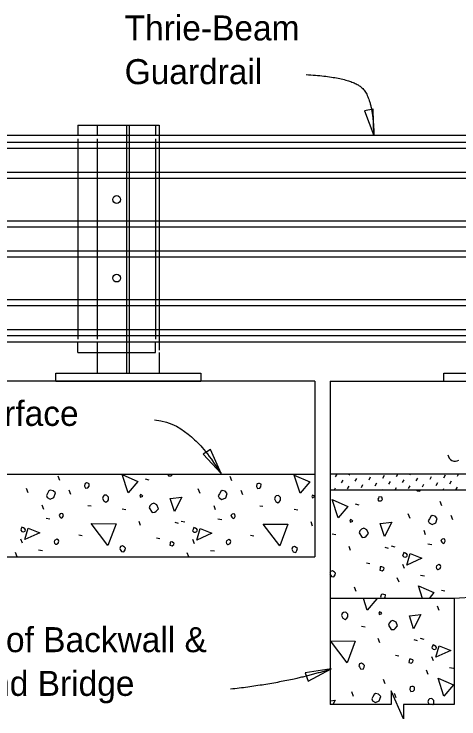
# Model space of a CAD drawing. Extents: x 21587 to 21659.1, y 56113.9 to 56155.9.
# Drawn here: x 21591.41 to 21595, y 56132.08 to 56137.76 of the extents above; entities that cross this region are included whole.
import ezdxf

# ---------------------------------------------------------------- set-up
doc = ezdxf.new("R2010")
doc.units = 0
for name, color, linetype in [('AdhocPoint_dp', 7, 'Continuous'), ('Border', 7, 'Continuous'), ('Patterning', 7, 'Continuous'), ('PlotBorder_dp', 7, 'Continuous'), ('SheetBorder_dp', 7, 'Continuous'), ('TextMisc', 7, 'Continuous')]:
    doc.layers.add(name, color=color, linetype=linetype)

msp = doc.modelspace()

# ---------------------------------------------------------------- linework, layer by layer
at = {"layer": 'AdhocPoint_dp'}
for p, q in [((21593.837, 56134.8009), (21587.6633, 56134.8009)), ((21593.837, 56134.8009), (21593.837, 56133.3842)), ((21593.9596, 56134.801), (21593.9596, 56132.1963)), ((21593.9596, 56134.8009), (21601.9067, 56134.8009)), ((21587.6633, 56134.0511), (21593.837, 56134.0511)), ((21604.323, 56134.0511), (21593.9596, 56134.0511)), ((21593.9596, 56133.926), (21604.323, 56133.926)), ((21587.6633, 56133.3843), (21593.837, 56133.3843)), ((21599.1795, 56133.301), (21594.9596, 56133.051)), ((21594.9596, 56133.051), (21593.9595, 56133.051)), ((21594.9596, 56133.051), (21594.9596, 56132.1963))]:
    msp.add_line(p, q, dxfattribs=at)
at = {"layer": 'Border'}
for p, q in [((21592.0846, 56136.8635), (21592.5846, 56136.8635)), ((21592.0846, 56136.8635), (21592.0846, 56136.7802)), ((21599.7592, 56136.7801), (21587.6633, 56136.7801)), ((21587.6633, 56136.7246), (21599.7592, 56136.7246)), ((21587.6633, 56136.6764), (21599.7592, 56136.6764)), ((21587.6633, 56136.4835), (21599.7592, 56136.4835)), ((21587.6633, 56136.4353), (21599.7592, 56136.4353)), ((21587.6633, 56136.0914), (21599.7592, 56136.0914)), ((21587.6633, 56136.0431), (21599.7592, 56136.0431)), ((21587.6633, 56135.8503), (21599.7592, 56135.8503)), ((21587.6633, 56135.8022), (21599.7592, 56135.8022)), ((21587.6633, 56135.4582), (21599.7592, 56135.4582)), ((21587.6633, 56135.41), (21599.7592, 56135.41)), ((21587.6633, 56135.2172), (21599.7592, 56135.2172)), ((21587.6633, 56135.169), (21599.7592, 56135.169)), ((21599.7592, 56135.1134), (21587.6633, 56135.1134)), ((21592.0846, 56135.1135), (21592.0846, 56134.8635)), ((21592.5846, 56135.0302), (21592.5846, 56134.8635)), ((21591.7513, 56134.8635), (21592.9179, 56134.8635)), ((21591.7513, 56134.801), (21591.7513, 56134.8635)), ((21592.0846, 56134.8635), (21592.5846, 56134.8635)), ((21592.9179, 56134.8635), (21592.9179, 56134.801)), ((21594.8762, 56134.8635), (21596.0429, 56134.8635)), ((21594.8762, 56134.801), (21594.8762, 56134.8635)), ((21591.7513, 56134.801), (21592.9179, 56134.801)), ((21594.8762, 56134.801), (21596.0429, 56134.801))]:
    msp.add_line(p, q, dxfattribs=at)
for centre in [(21592.2409, 56136.2634), (21592.2409, 56135.6303)]:
    msp.add_circle(centre, 0.0312, dxfattribs=at)
at = {"layer": 'Patterning'}
for p, q in [((21592.3242, 56134.8635), (21592.3242, 56136.8635)), ((21592.345, 56134.8635), (21592.345, 56136.8635)), ((21592.5846, 56136.8635), (21592.5846, 56135.0505)), ((21592.0846, 56136.7516), (21592.0846, 56135.1398))]:
    msp.add_line(p, q, dxfattribs=at)
at = {"layer": 'PlotBorder_dp'}
for points in [[(21594.3131, 56136.7801), (21594.3072, 56136.9912), (21594.238, 56136.9775)], [(21593.0824, 56134.0576), (21592.996, 56134.2503), (21592.9373, 56134.2111)], [(21593.9695, 56132.4823), (21593.7607, 56132.4504), (21593.7829, 56132.3835)]]:
    msp.add_lwpolyline(points, close=True, dxfattribs=at)
msp.add_lwpolyline([(21594.9596, 56132.1964), (21594.551, 56132.1964), (21594.551, 56132.0802), (21594.4516, 56132.3052), (21594.4516, 56132.1964), (21593.9596, 56132.1964)], dxfattribs=at)
msp.add_arc((21594.9683, 56134.2153), 0.0596, 187.9536, 299.6808, dxfattribs=at)
for points, degree in [([(21593.7688, 56137.2691), (21594.1402, 56137.2481), (21594.3083, 56137.0632), (21594.3131, 56136.7801)], 2), ([(21592.5456, 56134.4896), (21592.6874, 56134.4753), (21592.8643, 56134.3451), (21592.9617, 56134.2379), (21593.0824, 56134.0575)], 3), ([(21593.9695, 56132.4824), (21593.6416, 56132.3739), (21593.1591, 56132.319)], 2)]:
    msp.add_open_spline(points, degree=degree, dxfattribs=at)
at = {"layer": 'TextMisc'}
for p, q in [((21591.9284, 56136.8635), (21592.5534, 56136.8635)), ((21591.9284, 56136.8635), (21591.9284, 56136.7802)), ((21592.5534, 56136.8635), (21592.5534, 56136.7802)), ((21591.9284, 56136.7516), (21591.9284, 56135.1398)), ((21592.5534, 56136.7516), (21592.5534, 56135.1398)), ((21591.9284, 56135.0302), (21591.9284, 56135.1135)), ((21592.5534, 56135.0302), (21592.5534, 56135.1135)), ((21591.9284, 56135.0302), (21592.5534, 56135.0302)), ((21591.7845, 56134.0008), (21591.7703, 56134.0362)), ((21593.1691, 56133.9973), (21593.155, 56134.0326)), ((21594.004, 56134.0297), (21594.0163, 56134.0511)), ((21594.1146, 56134.0427), (21594.1194, 56134.0511)), ((21594.2741, 56134.0068), (21594.287, 56134.0292)), ((21594.3847, 56134.0198), (21594.3976, 56134.0422)), ((21594.4953, 56134.0328), (21594.5059, 56134.0511)), ((21594.606, 56134.0457), (21594.6091, 56134.0511)), ((21594.7654, 56134.0098), (21594.7784, 56134.0322)), ((21594.8761, 56134.0228), (21594.889, 56134.0452)), ((21594.9867, 56134.0358), (21594.9955, 56134.0511)), ((21592.4709, 56134.0132), (21592.4992, 56134.0061)), ((21594.0528, 56133.9809), (21594.0658, 56134.0033)), ((21594.1634, 56133.9939), (21594.1764, 56134.0163)), ((21594.3229, 56133.958), (21594.3359, 56133.9804)), ((21594.4335, 56133.971), (21594.4465, 56133.9933)), ((21594.5442, 56133.9839), (21594.5571, 56134.0063)), ((21594.6548, 56133.9969), (21594.6677, 56134.0193)), ((21594.8143, 56133.961), (21594.8272, 56133.9834)), ((21594.9249, 56133.974), (21594.9378, 56133.9964)), ((21591.5281, 56133.9), (21591.514, 56133.9354)), ((21591.8722, 56133.8883), (21591.8581, 56133.9237)), ((21592.9128, 56133.8965), (21592.8987, 56133.9319)), ((21593.2569, 56133.8848), (21593.2428, 56133.9201)), ((21593.995, 56133.926), (21594.004, 56133.9415)), ((21594.1016, 56133.9321), (21594.1146, 56133.9545)), ((21594.2123, 56133.945), (21594.2252, 56133.9674)), ((21594.3815, 56133.926), (21594.3847, 56133.9315)), ((21594.4846, 56133.926), (21594.4953, 56133.9445)), ((21594.593, 56133.9351), (21594.606, 56133.9575)), ((21594.7036, 56133.948), (21594.7166, 56133.9704)), ((21594.8711, 56133.926), (21594.8761, 56133.9346)), ((21594.9742, 56133.926), (21594.9867, 56133.9475)), ((21594.1625, 56133.8122), (21594.1907, 56133.8051)), ((21594.8607, 56133.7963), (21594.8466, 56133.8317)), ((21591.6536, 56133.7675), (21591.6413, 56133.801)), ((21592.0101, 56133.7999), (21592.0349, 56133.7964)), ((21592.2859, 56133.7716), (21592.3159, 56133.7663)), ((21593.0383, 56133.7639), (21593.026, 56133.7975)), ((21593.3948, 56133.7964), (21593.4195, 56133.7928)), ((21593.6706, 56133.7681), (21593.7006, 56133.7628)), ((21591.6725, 56133.6956), (21591.7025, 56133.6903)), ((21593.0571, 56133.6921), (21593.0872, 56133.6868)), ((21594.6044, 56133.6955), (21594.5903, 56133.7309)), ((21594.9485, 56133.6838), (21594.9343, 56133.7192)), ((21592.4344, 56133.6373), (21592.422, 56133.6709)), ((21592.7084, 56133.6638), (21592.7367, 56133.6567)), ((21592.7608, 56133.6738), (21592.7891, 56133.6667)), ((21593.8191, 56133.6337), (21593.8067, 56133.6673)), ((21594.7299, 56133.563), (21594.7175, 56133.5966)), ((21591.4822, 56133.4947), (21591.4698, 56133.5283)), ((21591.9359, 56133.563), (21591.9624, 56133.5577)), ((21592.5617, 56133.5383), (21592.5882, 56133.533)), ((21592.8669, 56133.4912), (21592.8545, 56133.5248)), ((21593.3205, 56133.5595), (21593.3471, 56133.5542)), ((21593.9775, 56133.5707), (21594.0075, 56133.5654)), ((21594.126, 56133.4363), (21594.1136, 56133.4699)), ((21594.4, 56133.4628), (21594.4282, 56133.4558)), ((21594.4524, 56133.4728), (21594.4806, 56133.4657)), ((21594.7487, 56133.4911), (21594.7788, 56133.4858)), ((21591.4397, 56133.3851), (21591.4256, 56133.4205)), ((21591.6124, 56133.4411), (21591.6442, 56133.4375)), ((21592.8233, 56133.3843), (21592.8103, 56133.4169)), ((21592.997, 56133.4375), (21593.0289, 56133.434)), ((21594.2532, 56133.3373), (21594.2797, 56133.332)), ((21594.5584, 56133.2902), (21594.5461, 56133.3238)), ((21594.6886, 56133.2366), (21594.7204, 56133.233)), ((21594.516, 56133.1806), (21594.5019, 56133.216)), ((21594.1701, 56133.1057), (21594.156, 56133.1411)), ((21594.8566, 56133.1181), (21594.8848, 56133.111)), ((21594.8391, 56132.9521), (21594.8249, 56132.9874)), ((21593.9595, 56132.8522), (21593.9611, 56132.8519)), ((21594.2122, 56132.8272), (21594.2422, 56132.8219)), ((21594.3606, 56132.6928), (21594.3483, 56132.7264)), ((21594.6871, 56132.7293), (21594.7153, 56132.7223)), ((21594.6347, 56132.7194), (21594.6629, 56132.7123)), ((21594.4879, 56132.5939), (21594.5144, 56132.5885)), ((21594.7931, 56132.5467), (21594.7807, 56132.5803)), ((21594.7507, 56132.4371), (21594.7366, 56132.4725)), ((21594.9233, 56132.4931), (21594.9551, 56132.4896)), ((21594.4048, 56132.3623), (21594.3907, 56132.3976)), ((21594.1485, 56132.2615), (21594.1344, 56132.2969)), ((21594.4926, 56132.2498), (21594.4785, 56132.2851))]:
    msp.add_line(p, q, dxfattribs=at)
for points in [[(21592.3336, 56133.9007), (21592.2859, 56134.0474), (21592.4114, 56133.9926), (21592.3336, 56133.9007)], [(21592.6533, 56134.0509), (21592.653, 56134.0503), (21592.6583, 56134.0379), (21592.6547, 56134.0415)], [(21592.6583, 56134.0379), (21592.6795, 56134.0379), (21592.6901, 56134.0485), (21592.6894, 56134.0509)], [(21593.7183, 56133.8971), (21593.6706, 56134.0439), (21593.7961, 56133.9891), (21593.7183, 56133.8971)], [(21591.9818, 56133.9555), (21591.9907, 56133.9396), (21592.0101, 56133.9413), (21592.0189, 56133.9537), (21592.0207, 56133.9731), (21592.0083, 56133.9785), (21591.9995, 56133.9802), (21591.9889, 56133.9767), (21591.9854, 56133.9731), (21591.9818, 56133.9555)], [(21593.3665, 56133.9519), (21593.3753, 56133.936), (21593.3948, 56133.9378), (21593.4036, 56133.9502), (21593.4054, 56133.9696), (21593.393, 56133.9749), (21593.3842, 56133.9767), (21593.3736, 56133.9731), (21593.37, 56133.9696), (21593.3665, 56133.9519)], [(21591.6819, 56133.8629), (21591.7049, 56133.8505), (21591.735, 56133.8629), (21591.7473, 56133.9), (21591.7297, 56133.9177), (21591.7067, 56133.923), (21591.6961, 56133.916), (21591.6837, 56133.8965), (21591.6749, 56133.8806), (21591.6819, 56133.8629)], [(21593.0666, 56133.8594), (21593.0896, 56133.847), (21593.1196, 56133.8594), (21593.132, 56133.8965), (21593.1143, 56133.9142), (21593.0914, 56133.9195), (21593.0808, 56133.9124), (21593.0684, 56133.893), (21593.0595, 56133.8771), (21593.0666, 56133.8594)], [(21594.6567, 56133.926), (21594.661, 56133.9183), (21594.6822, 56133.9147), (21594.6884, 56133.926)], [(21592.1268, 56133.8565), (21592.1374, 56133.8353), (21592.1551, 56133.8247), (21592.1692, 56133.8353), (21592.1763, 56133.8459), (21592.1763, 56133.8671), (21592.1604, 56133.883), (21592.1409, 56133.8812), (21592.1321, 56133.8724), (21592.1268, 56133.8565)], [(21592.4326, 56133.8653), (21592.4521, 56133.8742), (21592.445, 56133.8812), (21592.4326, 56133.8865), (21592.4273, 56133.8742), (21592.4326, 56133.8653)], [(21592.706, 56133.7498), (21592.6724, 56133.8541), (21592.7661, 56133.8665), (21592.706, 56133.7498)], [(21593.5115, 56133.8529), (21593.5221, 56133.8317), (21593.5397, 56133.8211), (21593.5539, 56133.8317), (21593.561, 56133.8423), (21593.561, 56133.8635), (21593.545, 56133.8795), (21593.5256, 56133.8777), (21593.5168, 56133.8689), (21593.5115, 56133.8529)], [(21593.8173, 56133.8618), (21593.8367, 56133.8706), (21593.8297, 56133.8777), (21593.8173, 56133.883), (21593.812, 56133.8706), (21593.8173, 56133.8618)], [(21594.3498, 56133.837), (21594.371, 56133.837), (21594.3817, 56133.8476), (21594.3764, 56133.867), (21594.3534, 56133.8688), (21594.3498, 56133.8582), (21594.3445, 56133.8493), (21594.3498, 56133.837), (21594.3463, 56133.8405)], [(21592.5033, 56133.7805), (21592.5263, 56133.7433), (21592.5493, 56133.7451), (21592.5581, 56133.7539), (21592.5776, 56133.7734), (21592.5652, 56133.8034), (21592.5404, 56133.8176), (21592.5228, 56133.8105), (21592.5086, 56133.7964), (21592.5033, 56133.7805)], [(21594.0252, 56133.6997), (21593.9775, 56133.8464), (21594.103, 56133.7916), (21594.0252, 56133.6997)], [(21591.7838, 56133.708), (21591.7944, 56133.6974), (21591.8051, 56133.7044), (21591.8121, 56133.7151), (21591.8086, 56133.7327), (21591.7997, 56133.7345), (21591.7874, 56133.7327), (21591.7768, 56133.7221), (21591.7838, 56133.708)], [(21593.1685, 56133.7044), (21593.1791, 56133.6938), (21593.1897, 56133.7009), (21593.1968, 56133.7115), (21593.1933, 56133.7292), (21593.1844, 56133.731), (21593.172, 56133.7292), (21593.1614, 56133.7186), (21593.1685, 56133.7044)], [(21594.7582, 56133.6584), (21594.7812, 56133.646), (21594.8112, 56133.6584), (21594.8236, 56133.6955), (21594.8059, 56133.7132), (21594.7829, 56133.7185), (21594.7723, 56133.7115), (21594.76, 56133.692), (21594.7511, 56133.6761), (21594.7582, 56133.6584)], [(21592.171, 56133.4764), (21592.0366, 56133.6532), (21592.2364, 56133.6514), (21592.171, 56133.4764)], [(21593.5557, 56133.4729), (21593.4213, 56133.6496), (21593.6211, 56133.6479), (21593.5557, 56133.4729)], [(21594.1242, 56133.6644), (21594.1436, 56133.6732), (21594.1366, 56133.6803), (21594.1242, 56133.6856), (21594.1189, 56133.6732), (21594.1242, 56133.6644)], [(21594.3976, 56133.5488), (21594.364, 56133.6531), (21594.4577, 56133.6655), (21594.3976, 56133.5488)], [(21591.4786, 56133.5889), (21591.491, 56133.5871), (21591.5034, 56133.5925), (21591.5069, 56133.6031), (21591.5016, 56133.6119), (21591.491, 56133.619), (21591.4786, 56133.6243), (21591.4716, 56133.6101), (21591.468, 56133.5995), (21591.4786, 56133.5889)], [(21591.501, 56133.5241), (21591.5293, 56133.6161), (21591.623, 56133.5789), (21591.501, 56133.5241)], [(21592.8633, 56133.5854), (21592.8757, 56133.5836), (21592.8881, 56133.5889), (21592.8916, 56133.5995), (21592.8863, 56133.6084), (21592.8757, 56133.6154), (21592.8633, 56133.6207), (21592.8562, 56133.6066), (21592.8527, 56133.596), (21592.8633, 56133.5854)], [(21592.8857, 56133.5206), (21592.914, 56133.6125), (21593.0076, 56133.5754), (21592.8857, 56133.5206)], [(21594.1949, 56133.5795), (21594.2179, 56133.5424), (21594.2409, 56133.5441), (21594.2497, 56133.553), (21594.2691, 56133.5724), (21594.2568, 56133.6025), (21594.232, 56133.6166), (21594.2143, 56133.6096), (21594.2002, 56133.5954), (21594.1949, 56133.5795)], [(21591.7485, 56133.4888), (21591.7556, 56133.4888), (21591.7697, 56133.4959), (21591.775, 56133.5118), (21591.7732, 56133.5206), (21591.7591, 56133.5277), (21591.7414, 56133.5171), (21591.7379, 56133.5065), (21591.7414, 56133.4959), (21591.7485, 56133.4888)], [(21593.1332, 56133.4852), (21593.1402, 56133.4852), (21593.1544, 56133.4923), (21593.1597, 56133.5082), (21593.1579, 56133.5171), (21593.1438, 56133.5241), (21593.1261, 56133.5135), (21593.1226, 56133.5029), (21593.1261, 56133.4923), (21593.1332, 56133.4852)], [(21594.8601, 56133.5035), (21594.8707, 56133.4929), (21594.8813, 56133.4999), (21594.8884, 56133.5106), (21594.8848, 56133.5282), (21594.876, 56133.53), (21594.8636, 56133.5282), (21594.853, 56133.5176), (21594.8601, 56133.5035)], [(21592.27, 56133.4446), (21592.2788, 56133.4287), (21592.3, 56133.4251), (21592.3089, 56133.4411), (21592.3124, 56133.4552), (21592.3036, 56133.464), (21592.2877, 56133.4729), (21592.2717, 56133.4676), (21592.2664, 56133.4517), (21592.27, 56133.4446)], [(21592.6695, 56133.4799), (21592.6889, 56133.4746), (21592.7013, 56133.4835), (21592.7031, 56133.4959), (21592.6995, 56133.4994), (21592.6854, 56133.5065), (21592.673, 56133.5047), (21592.6713, 56133.4923), (21592.6695, 56133.4799)], [(21593.6546, 56133.4411), (21593.6635, 56133.4251), (21593.6847, 56133.4216), (21593.6935, 56133.4375), (21593.6971, 56133.4517), (21593.6882, 56133.4605), (21593.6723, 56133.4693), (21593.6564, 56133.464), (21593.6511, 56133.4481), (21593.6546, 56133.4411)], [(21594.5549, 56133.3844), (21594.5673, 56133.3827), (21594.5796, 56133.388), (21594.5832, 56133.3986), (21594.5779, 56133.4074), (21594.5673, 56133.4145), (21594.5549, 56133.4198), (21594.5478, 56133.4056), (21594.5443, 56133.395), (21594.5549, 56133.3844)], [(21594.5773, 56133.3196), (21594.6055, 56133.4116), (21594.6992, 56133.3744), (21594.5773, 56133.3196)], [(21594.3611, 56133.279), (21594.3805, 56133.2737), (21594.3929, 56133.2825), (21594.3947, 56133.2949), (21594.3911, 56133.2984), (21594.377, 56133.3055), (21594.3646, 56133.3037), (21594.3628, 56133.2914), (21594.3611, 56133.279)], [(21594.8247, 56133.2843), (21594.8318, 56133.2843), (21594.846, 56133.2914), (21594.8513, 56133.3073), (21594.8495, 56133.3161), (21594.8353, 56133.3232), (21594.8177, 56133.3126), (21594.8141, 56133.302), (21594.8177, 56133.2914), (21594.8247, 56133.2843)], [(21593.9616, 56133.2436), (21593.9704, 56133.2277), (21593.9916, 56133.2242), (21594.0004, 56133.2401), (21594.004, 56133.2542), (21593.9951, 56133.2631), (21593.9792, 56133.2719), (21593.9633, 56133.2666), (21593.9595, 56133.2553)], [(21593.9595, 56133.2476), (21593.9616, 56133.2436)], [(21594.7045, 56133.051), (21594.6716, 56133.1523), (21594.7971, 56133.0975), (21594.7577, 56133.051)], [(21594.3992, 56133.051), (21594.4046, 56133.0586), (21594.4064, 56133.0781), (21594.394, 56133.0834), (21594.3852, 56133.0851), (21594.3746, 56133.0816), (21594.371, 56133.0781), (21594.3675, 56133.0604)], [(21594.2599, 56132.9562), (21594.2291, 56133.051)], [(21594.3312, 56133.051), (21594.3377, 56133.0482), (21594.2599, 56132.9562)], [(21594.3675, 56133.0604), (21594.3728, 56133.051)], [(21594.0531, 56132.912), (21594.0637, 56132.8908), (21594.0813, 56132.8802), (21594.0955, 56132.8908), (21594.1026, 56132.9014), (21594.1026, 56132.9227), (21594.0866, 56132.9386), (21594.0672, 56132.9368), (21594.0584, 56132.928), (21594.0531, 56132.912)], [(21594.3589, 56132.9209), (21594.3783, 56132.9297), (21594.3713, 56132.9368), (21594.3589, 56132.9421), (21594.3536, 56132.9297), (21594.3589, 56132.9209)], [(21594.6323, 56132.8054), (21594.5987, 56132.9097), (21594.6924, 56132.922), (21594.6323, 56132.8054)], [(21594.4296, 56132.836), (21594.4526, 56132.7989), (21594.4756, 56132.8007), (21594.4844, 56132.8095), (21594.5038, 56132.829), (21594.4915, 56132.859), (21594.4667, 56132.8732), (21594.449, 56132.8661), (21594.4349, 56132.8519), (21594.4296, 56132.836)], [(21594.0972, 56132.532), (21593.9629, 56132.7088), (21594.1627, 56132.707), (21594.0972, 56132.532)], [(21594.7896, 56132.641), (21594.802, 56132.6392), (21594.8143, 56132.6445), (21594.8179, 56132.6551), (21594.8126, 56132.6639), (21594.802, 56132.671), (21594.7896, 56132.6763), (21594.7825, 56132.6622), (21594.779, 56132.6516), (21594.7896, 56132.641)], [(21594.8119, 56132.5762), (21594.8402, 56132.6681), (21594.9339, 56132.631), (21594.8119, 56132.5762)], [(21594.5958, 56132.5355), (21594.6152, 56132.5302), (21594.6276, 56132.5391), (21594.6293, 56132.5514), (21594.6258, 56132.555), (21594.6117, 56132.562), (21594.5993, 56132.5603), (21594.5975, 56132.5479), (21594.5958, 56132.5355)], [(21594.1962, 56132.5002), (21594.2051, 56132.4842), (21594.2263, 56132.4807), (21594.2351, 56132.4966), (21594.2387, 56132.5108), (21594.2298, 56132.5196), (21594.2139, 56132.5284), (21594.198, 56132.5231), (21594.1927, 56132.5072), (21594.1962, 56132.5002)], [(21594.8774, 56132.2621), (21594.8297, 56132.4089), (21594.9552, 56132.3541), (21594.8774, 56132.2621)], [(21594.6022, 56132.3169), (21594.611, 56132.301), (21594.6305, 56132.3028), (21594.6393, 56132.3152), (21594.6411, 56132.3346), (21594.6287, 56132.3399), (21594.6199, 56132.3417), (21594.6093, 56132.3382), (21594.6057, 56132.3346), (21594.6022, 56132.3169)], [(21594.3023, 56132.2244), (21594.3253, 56132.212), (21594.3553, 56132.2244), (21594.3677, 56132.2615), (21594.35, 56132.2792), (21594.3271, 56132.2845), (21594.3165, 56132.2774), (21594.3041, 56132.258), (21594.2952, 56132.2421), (21594.3023, 56132.2244)], [(21593.9596, 56132.2259), (21594.0018, 56132.2315), (21593.9837, 56132.1963)], [(21594.7891, 56132.1964), (21594.7896, 56132.1967), (21594.7967, 56132.2073), (21594.7967, 56132.2285), (21594.7807, 56132.2445), (21594.7613, 56132.2427), (21594.7525, 56132.2339), (21594.7472, 56132.2179)], [(21594.7472, 56132.2179), (21594.7578, 56132.1967), (21594.7584, 56132.1964)]]:
    msp.add_lwpolyline(points, dxfattribs=at)

# ---------------------------------------------------------------- texts
at = {"layer": 'PlotBorder_dp'}
for s, p in [('Thrie-Beam ', (21592.3055, 56137.5444)), ('Guardrail', (21592.3055, 56137.1924)), ('Front Face of Backwall &', (21589.9713, 56132.6176)), ('Begin or End Bridge', (21589.9713, 56132.2656))]:
    msp.add_text(s, height=0.2016, dxfattribs=at).set_placement(p)
at = {"layer": 'SheetBorder_dp'}
msp.add_text('Final Riding Surface', height=0.2016, dxfattribs=at).set_placement((21589.5074, 56134.4399))

doc.saveas('drawing.dxf')
